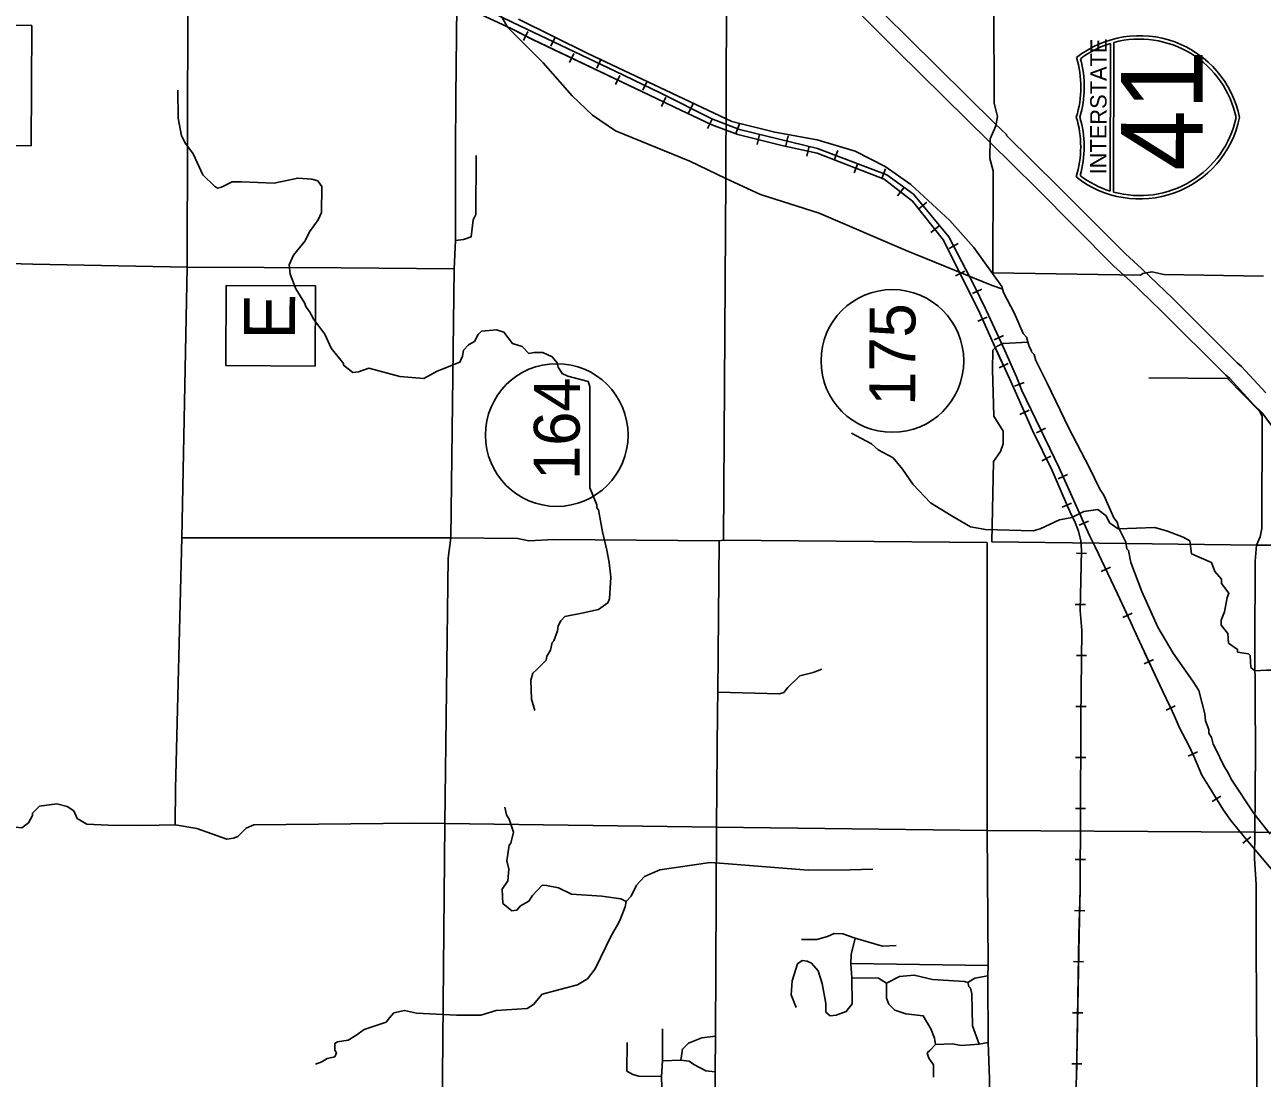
# Model space of a CAD drawing. Extents: x 299354 to 1325680, y 96128 to 228242.
# Drawn here: x 333137 to 357386, y 121836 to 142472 of the extents above; entities that cross this region are included whole.
import ezdxf

# ---------------------------------------------------------------- set-up
doc = ezdxf.new("R2010")
doc.units = 0
for name, color, linetype in [('Level 1', 7, 'Continuous'), ('Level 12', 7, 'Continuous'), ('Level 13', 7, 'Continuous'), ('Level 2', 7, 'Continuous'), ('Level 4', 7, 'Continuous'), ('Level 57', 7, 'Continuous'), ('Level 58', 7, 'Continuous')]:
    doc.layers.add(name, color=color, linetype=linetype)

msp = doc.modelspace()

# ---------------------------------------------------------------- linework, layer by layer
at = {"layer": 'Level 1'}
for points in [[(356203, 127772), (356044, 128142), (355946, 128351), (355766, 128703), (355668, 128929), (355578, 129113), (355431, 129423), (355080, 130179)], [(356203, 127772), (356045, 128142), (355947, 128351), (355767, 128703), (355669, 128929), (355579, 129113), (355432, 129423), (355081, 130179)], [(360579, 122351), (360571, 122359), (360117, 122922), (359597, 123543), (359259, 123946), (359077, 124140), (358813, 124442), (358425, 124854), (358293, 125038), (358022, 125399), (357601, 125895), (357064, 126525), (356768, 126886), (356628, 127087), (356332, 127565), (356203, 127772)], [(360578, 122351), (360570, 122359), (360116, 122922), (359596, 123543), (359258, 123946), (359077, 124140), (358812, 124442), (358424, 124854), (358293, 125038), (358021, 125399), (357600, 125895), (357064, 126525), (356767, 126886), (356627, 127087), (356331, 127565), (356203, 127772)]]:
    msp.add_lwpolyline(points, dxfattribs=at)
at = {"layer": 'Level 12'}
for p, q in [((354413, 142106), (354405, 139214)), ((354472, 139194), (354480, 142125)), ((350138, 135887), (350138, 135887)), ((343562, 134435), (343562, 134435))]:
    msp.add_line(p, q, dxfattribs=at)
for centre in [(350138, 135887), (343562, 134435)]:
    msp.add_circle(centre, 1398, dxfattribs=at)
for centre, radius, start, end in [((354981, 140259), 1999, 11.3832, 128.1773), ((354981, 140259), 1933, 107.1012, 126.8422), ((354981, 140259), 1933, 11.7868, 105.0434), ((351832, 141251), 1999, 342.8553, 16.8422), ((351832, 141251), 2066, 343.4192, 15.5586), ((351829, 140083), 1999, 342.8502, 16.8372), ((354983, 141058), 1999, 231.5152, 348.3093), ((351829, 140083), 2066, 344.1339, 16.2733), ((354983, 141058), 1933, 254.649, 347.9057), ((354983, 141058), 1933, 232.8503, 252.5912)]:
    msp.add_arc(centre, radius, start, end, dxfattribs=at)
at = {"layer": 'Level 13'}
msp.add_line((337934, 136609), (337934, 136609), dxfattribs=at)
for points in [[(333265, 140102), (331515, 140109), (331525, 142464), (333275, 142457)], [(338828, 135787), (337078, 135795), (337085, 137365), (338835, 137357)]]:
    msp.add_lwpolyline(points, close=True, dxfattribs=at)
at = {"layer": 'Level 2'}
for points in [[(344716, 147904), (344909, 147692), (345542, 147073), (346229, 146391), (347137, 145484), (347137, 145457), (347216, 145386), (349013, 143625), (349443, 143203), (349510, 143152), (350460, 142203), (352152, 140532), (352377, 140324), (352377, 140303), (353402, 139293), (354705, 137983), (355027, 137690), (355633, 137107), (356892, 135850), (356978, 135780), (357454, 135262)], [(344480, 147665), (344687, 147447), (345310, 146838), (345996, 146157), (348069, 144088), (348782, 143389), (349227, 142953), (349293, 142903), (350227, 141969), (352960, 139269), (354477, 137745), (354801, 137449), (355402, 136871), (356671, 135605), (356751, 135540), (357216, 135033), (357381, 134871), (358086, 133923), (358208, 133766), (358636, 133244), (358726, 133129)], [(341585, 141059), (341602, 142840)], [(342809, 142579), (344170, 141908), (346994, 140574), (347834, 140367), (348667, 140218), (349407, 139994), (349996, 139697), (350502, 139343), (351262, 138636), (351733, 138106), (352285, 137343), (352317, 137226), (352530, 136816), (352701, 136423), (352768, 136355), (352816, 136172), (352865, 136088), (352865, 136063), (352915, 136012), (352947, 135895), (353168, 135452), (353593, 134573), (353995, 133803), (354200, 133376), (354282, 133258), (354478, 132815), (354544, 132731), (354576, 132614), (354715, 132338), (354731, 132204), (354764, 132171), (354812, 131937), (355023, 131368), (355342, 130674), (355638, 130163), (356025, 129617), (356140, 129433), (356261, 128974), (356276, 128840), (356341, 128665), (356341, 128598), (356390, 128514), (356422, 128380), (356471, 128297), (356635, 127954), (356725, 127803), (356774, 127694), (357227, 127015), (357540, 126620)], [(341576, 140015), (341585, 141059)], [(341576, 140015), (341576, 138248)], [(341554, 137690), (341576, 138248)], [(332373, 137807), (333299, 137782), (336317, 137721)], [(336317, 137721), (339336, 137710)], [(339336, 137710), (341554, 137690)], [(341489, 132424), (341554, 137690)], [(341371, 126825), (341435, 132025), (341489, 132424)], [(357285, 132281), (357774, 132276), (358110, 132320), (358456, 132417), (358648, 132522)], [(354719, 132313), (357275, 132281)], [(341305, 119759), (341371, 126825)]]:
    msp.add_lwpolyline(points, dxfattribs=at)
at = {"layer": 'Level 4'}
for p, q in [((342907, 142164), (342996, 142343)), ((343445, 142050), (343530, 142231)), ((343810, 141730), (343896, 141911)), ((344349, 141622), (344434, 141803)), ((344713, 141300), (344799, 141481)), ((345248, 141188), (345336, 141368)), ((345615, 140870), (345701, 141051)), ((346144, 140745), (346233, 140924)), ((346518, 140440), (346604, 140621)), ((347069, 140344), (347140, 140531)), ((347487, 140126), (347535, 140320)), ((348051, 140099), (348099, 140294)), ((348464, 139900), (348506, 140095)), ((348996, 139820), (349068, 140006)), ((349389, 139570), (349461, 139756)), ((349930, 139461), (350001, 139648)), ((350238, 139119), (350361, 139277)), ((350657, 138866), (350811, 138994)), ((350894, 138404), (351050, 138529)), ((351250, 138091), (351427, 138184)), ((351377, 137557), (351556, 137646)), ((351708, 137206), (351888, 137293)), ((351814, 136664), (351998, 136744)), ((352133, 136303), (352314, 136386)), ((352228, 135751), (352409, 135835)), ((352533, 135392), (352719, 135466)), ((352635, 134840), (352818, 134920)), ((352960, 134481), (353141, 134567)), ((353064, 133932), (353243, 134020)), ((353388, 133580), (353571, 133662)), ((353467, 133023), (353651, 133102)), ((353800, 132668), (353982, 132751)), ((353745, 132119), (353945, 132114)), ((354229, 131764), (354410, 131849)), ((353722, 131119), (353922, 131115)), ((354654, 130859), (354835, 130943)), ((353744, 130119), (353944, 130117)), ((355075, 129952), (355257, 130036)), ((353735, 129119), (353935, 129117)), ((355500, 129045), (355680, 129132)), ((353729, 128119), (353929, 128118)), ((355933, 128145), (356114, 128230)), ((356406, 127254), (356576, 127359)), ((353725, 127119), (353925, 127118)), ((357006, 126438), (357159, 126567)), ((353721, 126119), (353921, 126118)), ((353707, 125121), (353907, 125116)), ((353685, 124120), (353885, 124117)), ((353669, 123120), (353869, 123117)), ((353652, 122121), (353852, 122116))]:
    msp.add_line(p, q, dxfattribs=at)
for points in [[(345598, 141129), (344709, 141562), (342700, 142513), (339487, 144080)], [(345513, 141030), (343089, 142185), (342682, 142389), (342159, 142635), (341486, 142966), (341013, 143187), (339429, 143967)], [(336332, 142872), (336317, 137721)], [(346890, 142875), (346875, 139459)], [(352127, 142845), (352134, 140936), (352199, 140677), (352164, 140494), (352053, 140237), (352049, 139854), (352114, 139611), (352104, 137611), (354997, 137569), (355048, 137601), (355223, 137633), (355456, 137581), (357407, 137547)], [(353701, 120055), (353755, 122204), (353794, 124646), (353819, 125537), (353831, 128654), (353833, 128879), (353849, 130604), (353819, 130996), (353847, 132179), (353832, 132362), (353783, 132554), (353718, 132722), (353612, 132939), (353465, 133282), (353269, 133742), (352884, 134521), (352623, 135117), (352435, 135542), (352206, 136035), (352091, 136278), (351854, 136822), (351142, 138254), (350532, 139017), (349977, 139447), (348664, 139959), (347973, 140107), (347108, 140323), (346601, 140511), (345870, 140860), (345513, 141030), (343089, 142185), (342682, 142389), (342159, 142635)], [(342352, 142817), (342352, 142767), (342500, 142599), (342599, 142423), (343293, 141725), (343862, 141078), (344259, 140699), (344715, 140395), (346169, 139799), (346875, 139459)], [(357600, 125895), (357064, 126525), (356767, 126886), (356627, 127087), (356331, 127565), (356203, 127772), (356044, 128142), (355946, 128351), (355766, 128703), (355668, 128929), (355578, 129113), (355431, 129423), (354981, 130394), (354809, 130762), (354548, 131322), (354114, 132243), (353999, 132469), (353403, 133791), (352674, 135306), (352569, 135574), (352340, 136093), (351980, 136871), (351955, 136921), (351743, 137365), (351243, 138319), (350550, 139151), (350028, 139530), (348673, 140051), (347142, 140423), (346602, 140628), (345598, 141129), (344709, 141562), (342700, 142513)], [(348673, 140051), (347142, 140423), (346602, 140628), (345598, 141129)], [(348664, 139959), (347973, 140107), (347108, 140323), (346601, 140511), (345870, 140860), (345513, 141030)], [(349977, 139447), (348664, 139959)], [(350028, 139530), (348673, 140051)], [(341576, 138248), (341735, 138264), (341885, 138321), (341922, 138654), (341973, 138753), (341984, 139911)], [(346875, 139459), (346826, 132376)], [(346875, 139459), (347556, 139144), (348703, 138784), (350406, 138052), (352093, 137362)], [(351142, 138254), (350532, 139017), (349977, 139447)], [(351243, 138319), (350550, 139151), (350028, 139530)], [(351854, 136822), (351142, 138254)], [(351980, 136871), (351955, 136921), (351743, 137365), (351243, 138319)], [(336218, 132422), (336317, 137721)], [(352093, 137362), (352301, 137293)], [(352623, 135117), (352435, 135542), (352206, 136035), (352091, 136278), (351854, 136822)], [(352674, 135306), (352569, 135574), (352340, 136093), (351980, 136871)], [(352088, 132345), (352120, 133920), (352255, 134110), (352306, 134260), (352309, 134510), (352128, 134803), (352103, 135720), (352106, 136095), (352190, 136177), (352308, 136226), (352800, 136255)], [(355162, 135559), (356705, 135545), (357333, 134906), (357382, 134805), (357378, 132605), (357343, 132439), (357275, 132281)], [(353403, 133791), (352674, 135306)], [(353269, 133742), (352884, 134521), (352623, 135117)], [(353847, 132179), (353832, 132362), (353783, 132554), (353718, 132722), (353612, 132939), (353465, 133282), (353269, 133742)], [(354809, 130762), (354548, 131322), (354114, 132243), (353999, 132469), (353403, 133791)], [(336090, 127514), (336218, 132422)], [(336218, 132422), (341489, 132424)], [(341489, 132424), (342798, 132412), (343015, 132360), (343507, 132389), (346743, 132360)], [(346715, 129402), (346743, 132360)], [(346743, 132360), (346826, 132376)], [(346826, 132376), (351996, 132329)], [(351996, 132329), (351994, 126687)], [(352088, 132345), (354718, 132313)], [(353819, 130996), (353847, 132179)], [(357275, 132281), (357247, 131965), (357240, 130265), (357255, 128240), (357240, 126656)], [(353833, 128879), (353849, 130604), (353819, 130996)], [(356203, 127772), (356044, 128142), (355946, 128351), (355766, 128703), (355668, 128929), (355578, 129113), (355431, 129423), (354981, 130394), (354809, 130762)], [(346715, 129402), (347924, 129366), (348008, 129390), (348092, 129489), (348328, 129720), (348587, 129785), (348754, 129850)], [(346712, 129036), (346715, 129402)], [(346691, 126752), (346712, 129036)], [(353819, 125537), (353831, 128654), (353833, 128879)], [(360578, 122351), (360570, 122359), (360116, 122922), (359596, 123543), (359258, 123946), (359077, 124140), (358812, 124442), (358424, 124854), (358293, 125038), (358021, 125399), (357600, 125895), (357064, 126525), (356767, 126886), (356627, 127087), (356331, 127565), (356203, 127772)], [(336083, 126798), (336090, 127514)], [(330929, 126795), (332713, 126778), (333080, 126742), (333214, 126840), (333291, 126981), (333291, 127031), (333426, 127164), (333768, 127210), (333968, 127159), (334101, 127074), (334166, 126924), (334357, 126813), (334774, 126793)], [(336083, 126798), (336508, 126727), (337098, 126522), (337231, 126537), (337315, 126570), (337475, 126735), (337626, 126801), (340795, 126830), (341371, 126825)], [(341371, 126825), (346691, 126752)], [(334774, 126793), (335457, 126787)], [(335457, 126787), (336083, 126798)], [(346691, 126752), (346670, 122660)], [(346691, 126752), (351994, 126687)], [(351994, 126687), (352012, 124045)], [(351994, 126687), (357240, 126656)], [(357240, 126656), (357235, 126131), (357264, 125631), (357266, 124535)], [(357240, 126656), (362589, 126584)], [(353755, 122204), (353794, 124646), (353819, 125537)], [(348355, 124553), (348655, 124551), (348865, 124615), (348999, 124673), (349165, 124663), (349406, 124577)], [(349327, 124086), (349328, 124261), (349406, 124577)], [(349406, 124577), (349947, 124422), (350214, 124437)], [(357266, 124535), (357296, 118256)], [(348251, 123221), (348153, 123472), (348173, 123747), (348276, 124079), (348368, 124145), (348468, 124127), (348551, 124093), (348683, 123942), (348764, 123691), (348836, 123299), (348834, 123132), (348917, 123057), (349034, 123072), (349235, 123145), (349353, 123294), (349341, 123803)], [(349327, 124086), (349341, 123803)], [(349327, 124086), (352012, 124045)], [(352010, 123845), (352012, 124045)], [(349341, 123803), (349866, 123798), (350024, 123697)], [(350024, 123697), (350021, 123405), (350070, 123288), (350186, 123170), (350402, 123101), (350743, 123057), (350891, 122805), (350964, 122621), (350980, 122496)], [(350024, 123697), (350275, 123828), (350567, 123858), (350925, 123772), (351550, 123733), (351617, 123715)], [(351617, 123715), (351751, 123798), (352010, 123845)], [(351617, 123715), (351633, 123632), (351666, 123598), (351698, 123490), (351709, 122865), (351839, 122505)], [(352010, 123845), (352015, 122496)], [(345631, 122178), (345637, 122803)], [(344942, 122534), (344937, 121976), (345053, 121908), (345170, 121874), (345612, 121870)], [(345990, 122191), (346025, 122408), (346143, 122523), (346403, 122629), (346670, 122660)], [(346663, 121960), (346670, 122660)], [(350941, 121855), (350943, 122097), (350852, 122231), (350820, 122331), (350871, 122381), (350980, 122496)], [(350980, 122496), (351314, 122510), (351489, 122475), (351839, 122505)], [(351839, 122505), (352015, 122537)], [(352015, 122537), (352041, 121828), (352032, 118970)], [(345612, 121870), (345631, 122178)], [(345631, 122178), (345990, 122191)], [(345990, 122191), (346157, 122173), (346248, 122106), (346480, 121979), (346663, 121960)], [(353574, 118881), (353646, 119447), (353701, 120055), (353755, 122204)], [(345612, 121870), (345624, 121445)], [(346650, 120527), (346663, 121960)]]:
    msp.add_lwpolyline(points, dxfattribs=at)
at = {"layer": 'Level 57'}
for points in [[(336140, 141189), (336145, 140639), (336208, 140297), (336290, 140146), (336439, 139945), (336627, 139535), (336858, 139308), (336916, 139274)], [(336916, 139274), (336991, 139290), (337201, 139396), (337384, 139395), (338026, 139372), (338486, 139468), (338761, 139449), (338877, 139415), (338960, 139306), (338955, 138797), (338887, 138648), (338718, 138416), (338633, 138242), (338405, 137960), (338320, 137770), (338335, 137586), (338449, 137302), (338622, 137025), (338654, 136942), (338720, 136858), (338802, 136699), (339016, 136413), (339139, 136137), (339386, 135835), (339386, 135802), (339568, 135658), (339677, 135674), (339878, 135747), (340485, 135583), (340960, 135546), (341220, 135685), (341664, 135864), (341715, 135980), (341732, 136097), (341833, 136204), (341951, 136270), (342019, 136403), (342086, 136469), (342378, 136499), (342528, 136448), (342693, 136230), (342884, 136170), (343016, 136035), (343116, 136051), (343291, 136050), (343474, 135965), (343573, 135847), (343589, 135764), (343671, 135638), (343779, 135587), (344179, 135483), (344211, 135383), (344209, 133399), (344348, 133065), (344348, 133007), (344381, 132973), (344460, 132539), (344540, 132180), (344588, 131938), (344619, 131654), (344598, 131229), (344564, 131146), (344379, 131015), (344053, 130943), (343719, 130879), (343643, 130796), (343592, 130697), (343575, 130597), (343506, 130406), (343473, 130373), (343438, 130223), (343370, 130107), (343353, 130024), (343167, 129834), (343092, 129768), (343057, 129635), (343070, 129260), (343135, 129042)], [(349340, 134470), (349730, 134266), (349862, 134148), (350153, 133987), (350334, 133769), (350540, 133476), (350887, 133106), (351293, 132860), (351667, 132640), (351966, 132588), (352900, 132562), (353034, 132595), (353411, 132775), (353653, 132822), (353888, 132937), (354163, 132976), (354329, 132850), (354394, 132716), (354560, 132597), (355278, 132624), (355527, 132555), (355835, 132436), (355967, 132360), (355998, 132109), (356389, 131939), (356454, 131764), (356586, 131612), (356585, 131529), (356734, 131336), (356699, 131253), (356647, 130970), (356579, 130812), (356578, 130712), (356710, 130545), (356725, 130361), (356899, 130235), (356898, 130185)], [(356898, 130185), (357115, 130149), (357148, 130116), (357162, 129882), (357237, 129815), (357470, 129829), (357720, 129827), (358061, 129716), (358317, 129413), (358466, 129329), (358908, 129266), (359024, 129182), (359258, 129196), (359783, 129208), (361568, 129209)], [(342543, 127146), (342574, 126997), (342632, 126914), (342713, 126655), (342661, 126438), (342627, 126405), (342582, 126097), (342623, 125930), (342604, 125705), (342494, 125540), (342508, 125256)], [(344919, 125301), (345020, 125400), (345122, 125616), (345282, 125790), (345583, 125920), (346569, 126061), (346844, 126042), (348485, 125911), (349311, 125920)], [(349311, 125920), (349753, 125932)], [(342508, 125256), (342682, 125113), (342782, 125129), (342850, 125212), (343017, 125302), (343085, 125418), (343279, 125616), (343362, 125615), (343595, 125563), (343852, 125444), (344444, 125405), (344819, 125352), (344919, 125301)], [(338834, 122115), (338960, 122155), (339061, 122221), (339211, 122253), (339245, 122336), (339212, 122386), (339213, 122519), (339264, 122552), (339473, 122584), (339624, 122674), (339791, 122789), (340218, 122935), (340286, 123018), (340370, 123117), (340579, 123165), (340812, 123113), (341595, 123073), (342071, 123069), (342372, 123166), (342981, 123202), (343107, 123284), (343276, 123483), (343970, 123668), (344162, 123783), (344314, 123982), (344637, 124637), (344747, 124828), (344798, 124927), (344901, 125193), (344919, 125301)]]:
    msp.add_lwpolyline(points, dxfattribs=at)
at = {"layer": 'Level 58'}
for points in [[(345513, 141030), (343089, 142185), (342682, 142389), (342159, 142635), (341486, 142966), (341013, 143187), (339429, 143967)], [(345514, 141030), (343090, 142185), (342683, 142389), (342160, 142635), (341487, 142966), (341014, 143187), (339430, 143967)], [(348664, 139959), (347973, 140107), (347108, 140323), (346601, 140511), (345870, 140860), (345513, 141030)], [(348665, 139959), (347974, 140107), (347109, 140323), (346602, 140511), (345871, 140860), (345514, 141030)], [(349977, 139447), (348664, 139959)], [(349978, 139447), (348665, 139959)], [(351142, 138254), (350532, 139017), (349977, 139447)], [(351143, 138254), (350533, 139017), (349978, 139447)], [(351854, 136822), (351142, 138254)], [(351855, 136822), (351143, 138254)], [(352623, 135117), (352435, 135542), (352206, 136035), (352091, 136278), (351854, 136822)], [(352624, 135117), (352436, 135542), (352207, 136036), (352092, 136278), (351855, 136822)], [(353269, 133742), (352884, 134521), (352623, 135117)], [(353270, 133742), (352885, 134521), (352624, 135117)], [(353847, 132179), (353832, 132362), (353783, 132554), (353718, 132722), (353612, 132939), (353465, 133282), (353269, 133742)], [(353847, 132179), (353832, 132362), (353784, 132554), (353719, 132722), (353613, 132939), (353466, 133282), (353270, 133742)], [(353819, 130996), (353847, 132179)], [(353820, 130996), (353847, 132179)], [(353833, 128879), (353849, 130604), (353819, 130996)], [(353834, 128879), (353850, 130604), (353820, 130996)], [(353819, 125537), (353831, 128654), (353833, 128879)], [(353820, 125537), (353832, 128654), (353834, 128879)], [(353755, 122204), (353795, 124646), (353820, 125537)], [(353755, 122204), (353794, 124646), (353819, 125537)], [(353749, 121985), (353755, 122204)], [(353750, 121985), (353755, 122204)]]:
    msp.add_lwpolyline(points, dxfattribs=at)

# ---------------------------------------------------------------- texts
at = {"layer": 'Level 12'}
for s, height, rotation, p in [('INTERSTATE', 319.9, 89.8462, (354331, 139540)), ('41', 1599.6, 89.8462, (356214, 139607)), ('175', 900, 89.767, (350584, 135007)), ('164', 900, 89.767, (344008, 133555))]:
    msp.add_text(s, height=height, rotation=rotation, dxfattribs=at).set_placement(p)
at = {"layer": 'Level 13'}
msp.add_text('E', height=1000, rotation=89.767, dxfattribs=at).set_placement((338433, 136304))

doc.saveas('drawing.dxf')
